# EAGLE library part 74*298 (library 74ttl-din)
Quadruple 2-input MULTIPLEXER
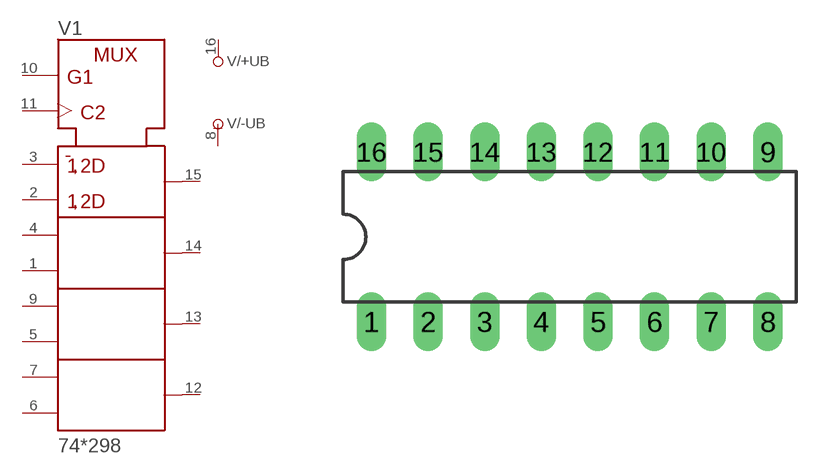
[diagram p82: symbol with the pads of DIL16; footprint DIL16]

Designator prefix V; gates /+UB=+UB /-UB=-UB 1=298

## 74298N  [DIL16]
1  1:B2  in
2  1:A2  in
3  1:A1  in
4  1:B1  in
5  1:C2  in
6  1:D2  in
7  1:D1  in
8  /-UB:-UB  pwr
9  1:C1  in
10  1:WS  in
11  1:CLK  in
12  1:QD  out
13  1:QC  out
14  1:QB  out
15  1:QA  out
16  /+UB:+UB  pwr

## Footprint DIL16 (pad centres in mm)
Dual In Line Package
drill 0.813 long: 1 -8.89,-3.81; 2 -6.35,-3.81; 3 -3.81,-3.81; 4 -1.27,-3.81; 5 1.27,-3.81; 6 3.81,-3.81; 7 6.35,-3.81; 8 8.89,-3.81; 9 8.89,3.81; 10 6.35,3.81; 11 3.81,3.81; 12 1.27,3.81; 13 -1.27,3.81; 14 -3.81,3.81; 15 -6.35,3.81; 16 -8.89,3.81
